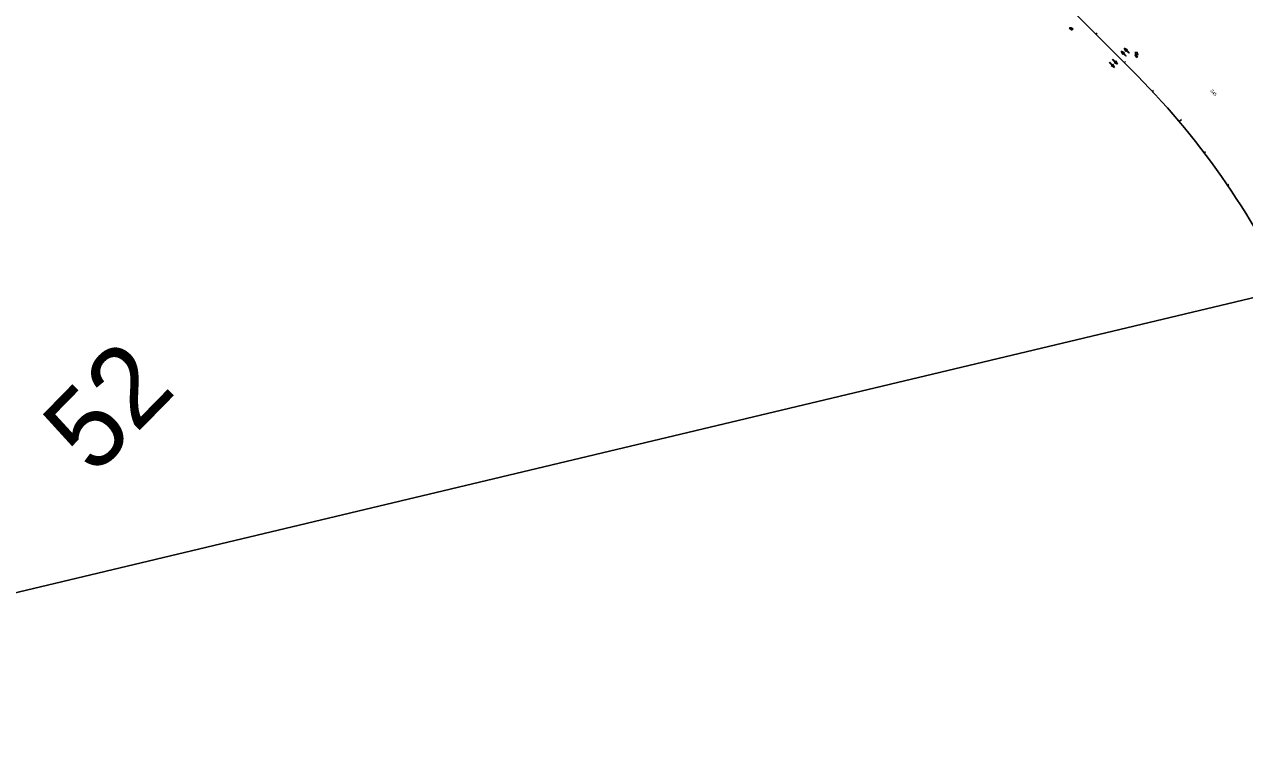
# Model space of a CAD drawing. Extents: x -5665 to 1997148, y 4 to 827579.
# Drawn here: x 1969802 to 1972838, y 800080 to 801861 of the extents above; entities that cross this region are included whole.
import ezdxf

# ---------------------------------------------------------------- set-up
doc = ezdxf.new("R2010")
doc.units = 0
for name, color, linetype in [('RD_HC_CL_Rel', 7, 'Continuous'), ('RD_HC_Data_Tic_Rel', 7, 'Continuous'), ('RD_HC_TX_Rel_Sta50', 7, 'Continuous'), ('RD_PD_SW', 7, 'Continuous'), ('RD_SHT_ShtClip', 7, 'Continuous'), ('RD_SHT_TX', 7, 'Continuous'), ('RD_Sketch8', 7, 'Continuous')]:
    doc.layers.add(name, color=color, linetype=linetype)

msp = doc.modelspace()

# ---------------------------------------------------------------- linework, layer by layer
at = {"layer": 'RD_HC_CL_Rel'}
msp.add_line((1972119.3, 802188), (1972571.3, 801733), dxfattribs=at)
msp.add_arc((1971216.4, 800387), 1909.9, 23.8711, 44.8091, dxfattribs=at)
at = {"layer": 'RD_HC_Data_Tic_Rel'}
for p, q in [((1972468.2, 801836.8), (1972471, 801839.6)), ((1972538.6, 801765.9), (1972541.5, 801768.7)), ((1972608.6, 801694.4), (1972611.5, 801697.1)), ((1972675.1, 801619.7), (1972681.2, 801624.9)), ((1972737.6, 801541.7), (1972740.8, 801544.1)), ((1972796, 801460.5), (1972799.3, 801462.8))]:
    msp.add_line(p, q, dxfattribs=at)
at = {"layer": 'RD_PD_SW'}
for p, q in [((1972408, 801846.8), (1972401.8, 801853)), ((1972402.2, 801852.5), (1972408, 801846.8)), ((1972411.7, 801850.4), (1972408, 801846.8)), ((1972408, 801846.8), (1972411.3, 801850.1))]:
    msp.add_line(p, q, dxfattribs=at)
msp.add_lwpolyline([(1972408.9, 801852.1), (1972404, 801853), (1972403.7, 801851.4), (1972408.6, 801850.5)], close=True, dxfattribs=at)
for centre, radius in [((1972404.1, 801851.6), 0.146), ((1972404.2, 801852.1), 0.146), ((1972404.1, 801851.6), 0.073), ((1972404.3, 801852.6), 0.146), ((1972404.2, 801852.1), 0.073), ((1972404.3, 801852.6), 0.073), ((1972404.5, 801851.6), 0.146), ((1972404.6, 801852.1), 0.146), ((1972404.5, 801851.6), 0.073), ((1972404.7, 801852.6), 0.146), ((1972404.6, 801852.1), 0.073), ((1972404.7, 801852.6), 0.073), ((1972404.9, 801851.5), 0.146), ((1972405, 801852), 0.146), ((1972404.9, 801851.5), 0.073), ((1972405.1, 801852.5), 0.146), ((1972405, 801852), 0.073), ((1972405.1, 801852.5), 0.073), ((1972405.3, 801851.4), 0.146), ((1972405.4, 801851.9), 0.146), ((1972405.3, 801851.4), 0.073), ((1972405.5, 801852.4), 0.146), ((1972405.4, 801851.9), 0.073), ((1972405.5, 801852.4), 0.073), ((1972405.7, 801851.4), 0.146), ((1972405.8, 801851.8), 0.146), ((1972405.7, 801851.4), 0.073), ((1972405.8, 801852.4), 0.146), ((1972405.8, 801851.8), 0.073), ((1972405.8, 801852.4), 0.073), ((1972406.1, 801851.3), 0.146), ((1972406.1, 801851.8), 0.146), ((1972406.1, 801851.3), 0.073), ((1972406.2, 801852.3), 0.146), ((1972406.1, 801851.8), 0.073), ((1972406.2, 801852.3), 0.073), ((1972406.5, 801851.2), 0.146), ((1972406.5, 801851.7), 0.146), ((1972406.5, 801851.2), 0.073), ((1972406.6, 801852.2), 0.146), ((1972406.5, 801851.7), 0.073), ((1972406.6, 801852.2), 0.073), ((1972406.8, 801851.1), 0.146), ((1972406.9, 801851.6), 0.146), ((1972406.8, 801851.1), 0.073), ((1972407, 801852.1), 0.146), ((1972406.9, 801851.6), 0.073), ((1972407, 801852.1), 0.073), ((1972407.2, 801851.1), 0.146), ((1972407.3, 801851.6), 0.146), ((1972407.2, 801851.1), 0.073), ((1972407.4, 801852.1), 0.146), ((1972407.4, 801852.1), 0.073), ((1972407.3, 801851.6), 0.073), ((1972407.6, 801851), 0.146), ((1972407.7, 801851.5), 0.073), ((1972407.7, 801851.5), 0.146), ((1972407.6, 801851), 0.073), ((1972407.8, 801852), 0.073), ((1972407.8, 801852), 0.146), ((1972408, 801850.9), 0.146), ((1972408.1, 801851.4), 0.146), ((1972408.1, 801851.4), 0.073), ((1972408, 801850.9), 0.073), ((1972408.2, 801851.9), 0.146), ((1972408.2, 801851.9), 0.073), ((1972408.4, 801850.9), 0.146), ((1972408.4, 801850.9), 0.073), ((1972408.5, 801851.3), 0.146), ((1972408.5, 801851.3), 0.073), ((1972408.6, 801851.8), 0.146), ((1972408.6, 801851.8), 0.073)]:
    msp.add_circle(centre, radius, dxfattribs=at)
for start in [44.9947, 45.0045]:
    msp.add_arc((1972404.6, 801843.3), 9.5, start, 104.5021, dxfattribs=at)
at = {"layer": 'RD_SHT_ShtClip'}
msp.add_lwpolyline([(1967695.1, 802969), (1968000.2, 801689.9), (1968522.9, 801587.9), (1968575.1, 801281.2), (1968568.4, 800839.6), (1968542.7, 800594.7), (1968247.7, 800080.4), (1974570.3, 801588.8), (1974094.7, 803428), (1973692.8, 804229.2), (1973344.3, 805614.1), (1967347.3, 804183.5), (1967746.1, 803578.5)], close=True, dxfattribs=at)
at = {"layer": 'RD_Sketch8'}
for p, q in [((1972535.3, 801786.5), (1972531.1, 801794.9)), ((1972531.1, 801794.9), (1972539.5, 801790.6)), ((1972535.6, 801789.1), (1972535.3, 801786.5)), ((1972542.4, 801782.3), (1972535.6, 801789.1)), ((1972539.5, 801790.6), (1972536.9, 801790.4)), ((1972536.9, 801790.4), (1972543.7, 801783.5)), ((1972542.9, 801794), (1972538.7, 801802.5)), ((1972538.7, 801802.5), (1972547.1, 801798.1)), ((1972543.2, 801796.6), (1972542.9, 801794)), ((1972550, 801789.8), (1972543.2, 801796.6)), ((1972547.1, 801798.1), (1972544.5, 801797.9)), ((1972544.5, 801797.9), (1972551.2, 801791.1)), ((1972551.2, 801791.1), (1972550, 801789.8)), ((1972564.8, 801791.4), (1972571, 801792)), ((1972564.8, 801791.4), (1972571, 801792)), ((1972568.1, 801789.7), (1972564.8, 801791.4)), ((1972568.1, 801789.7), (1972564.8, 801791.4)), ((1972567.4, 801789), (1972568.1, 801789.7)), ((1972567.4, 801789), (1972568.1, 801789.7)), ((1972570, 801788), (1972569.4, 801787.3)), ((1972570, 801788), (1972569.4, 801787.3)), ((1972572.4, 801785.2), (1972570, 801788)), ((1972572.4, 801785.2), (1972570, 801788)), ((1972571, 801792), (1972572.4, 801785.2)), ((1972571, 801792), (1972572.4, 801785.2)), ((1972501.7, 801765.8), (1972503, 801767)), ((1972508.5, 801759), (1972501.7, 801765.8)), ((1972503, 801767), (1972509.8, 801760.2)), ((1972505.8, 801758.7), (1972508.5, 801759)), ((1972514.3, 801754.4), (1972505.8, 801758.7)), ((1972509.4, 801773.4), (1972510.6, 801774.6)), ((1972516.1, 801766.6), (1972509.4, 801773.4)), ((1972509.8, 801760.2), (1972510, 801762.8)), ((1972510, 801762.8), (1972514.3, 801754.4)), ((1972510.6, 801774.6), (1972517.4, 801767.8)), ((1972513.5, 801766.3), (1972516.1, 801766.6)), ((1972521.9, 801762), (1972513.5, 801766.3)), ((1972517.4, 801767.8), (1972517.7, 801770.5)), ((1972517.7, 801770.5), (1972521.9, 801762)), ((1972543.7, 801783.5), (1972542.4, 801782.3)), ((1972571, 801778.9), (1972567.9, 801781.6)), ((1972571, 801778.9), (1972567.9, 801781.6)), ((1972569.7, 801782.2), (1972572.1, 801780.1)), ((1972569.7, 801782.2), (1972572.1, 801780.1)), ((1972572.1, 801780.1), (1972571, 801778.9)), ((1972572.1, 801780.1), (1972571, 801778.9)), ((1972572.1, 801780.1), (1972572.1, 801780.1)), ((1972572.1, 801780.1), (1972572.1, 801780.1))]:
    msp.add_line(p, q, dxfattribs=at)
for centre, radius, start, end in [((1972571.4, 801785.6), 5.29, 139.3696, 228.2122), ((1972571.4, 801785.6), 5.29, 139.3696, 228.2122), ((1972572, 801784.9), 3.56, 138.1739, 229.9367), ((1972572, 801784.9), 3.56, 138.1739, 229.9367)]:
    msp.add_arc(centre, radius, start, end, dxfattribs=at)

# ---------------------------------------------------------------- texts
at = {"layer": 'RD_HC_TX_Rel_Sta50'}
msp.add_text('245', height=8, rotation=310.2006, dxfattribs=at).set_placement((1972752.1, 801695.9))
at = {"layer": 'RD_SHT_TX'}
msp.add_text('52', height=200, rotation=45.6376, dxfattribs=at).set_placement((1969975.4, 800734.8))

doc.saveas('drawing.dxf')
